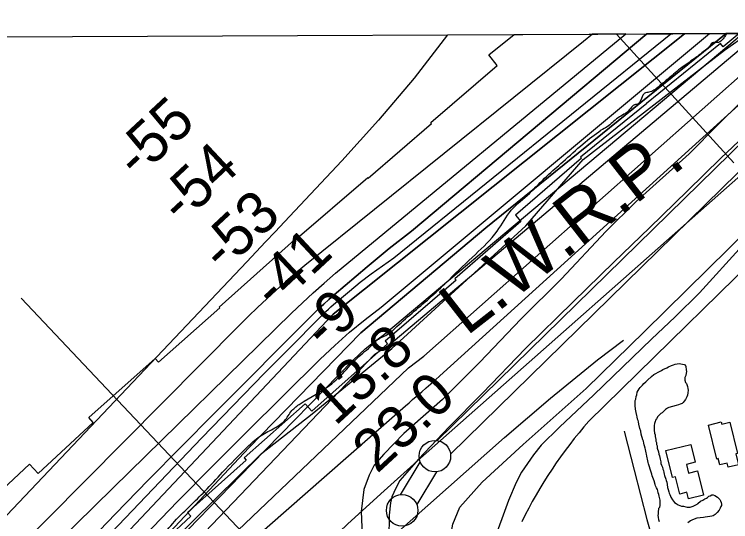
# Model space of a CAD drawing. Extents: x 3424494 to 3462436, y 522220 to 547718.
# Drawn here: x 3452339 to 3453473, y 545132 to 545936 of the extents above; entities that cross this region are included whole.
import ezdxf

# ---------------------------------------------------------------- set-up
doc = ezdxf.new("R2010")
doc.units = 0
for name, color, linetype in [('V-BLDG-OTLN', 7, 'Continuous'), ('V-DTCH-CNTR', 7, 'Continuous'), ('V-FLOD-BASE', 7, 'Continuous'), ('V-GRID-FRAM', 7, 'Continuous'), ('V-LEVE-TOET', 7, 'Continuous'), ('V-RIVR-EDGE', 7, 'Continuous'), ('V-RIVR-RANG', 7, 'Continuous'), ('V-ROAD-CNTR', 7, 'Continuous'), ('V-RRAP-FSHR', 7, 'Continuous'), ('V-RRAP-RVMT', 7, 'Continuous'), ('V-SITE-VEGE', 7, 'Continuous'), ('V-SURV-LINE', 7, 'Continuous'), ('V-TOPO-DPTH', 7, 'Continuous'), ('V-TOPO-MAJR', 7, 'Continuous'), ('V-TOPO-MINR', 7, 'Continuous'), ('V-TOPO-SHOR', 7, 'Continuous'), ('V-TOPO-WATR', 7, 'Continuous'), ('V-TOPO-WATR-IDEN', 7, 'Continuous')]:
    doc.layers.add(name, color=color, linetype=linetype)

msp = doc.modelspace()

# ---------------------------------------------------------------- linework, layer by layer
at = {"layer": 'V-BLDG-OTLN'}
for points in [[(3453450.9, 545231.5), (3453437.9, 545285.3), (3453458.2, 545290.2), (3453459.1, 545286.6), (3453472, 545289.7), (3453484, 545240.3), (3453481.1, 545239.6), (3453485.2, 545222.5), (3453469, 545218.6), (3453467.4, 545225), (3453455.9, 545222.2), (3453453.4, 545232.2)], [(3453380.8, 545202.2), (3453370.2, 545244.8), (3453410, 545254.7), (3453417, 545226.6), (3453402.9, 545223.1), (3453406.4, 545209.1), (3453420.5, 545212.6), (3453430, 545174.5), (3453406.2, 545168.6), (3453403.7, 545178.8), (3453392.4, 545176), (3453385.6, 545203.3)]]:
    msp.add_lwpolyline(points, close=True, dxfattribs=at)
at = {"layer": 'V-DTCH-CNTR'}
msp.add_lwpolyline([(3453304.6, 545275.4), (3453320.2, 545213.7), (3453340.6, 545136), (3453362.8, 545056.4), (3453380.1, 544985), (3453401.2, 544903.1)], dxfattribs=at)
at = {"layer": 'V-FLOD-BASE'}
msp.add_lwpolyline([(3453668.4, 545906.4), (3453642.8, 545882.8), (3453583.2, 545827), (3453524.7, 545771.6), (3453457.6, 545707.8), (3453404.9, 545656.2), (3453344.5, 545597.7), (3453287.9, 545543.1), (3453223.6, 545480.4), (3453148.5, 545406.8), (3453080.1, 545335.7), (3453027.5, 545282.5), (3452979.1, 545231.2), (3452949.6, 545197.7), (3452942.8, 545185.5), (3452936.8, 545171.7), (3452934.7, 545162.4), (3452932.4, 545142.8), (3452931.8, 545105.7), (3452934.7, 545024.5), (3452935.5, 544935.7), (3452937.9, 544845.3)], dxfattribs=at)
at = {"layer": 'V-GRID-FRAM'}
msp.add_lwpolyline([(3428547.8, 545793.2), (3460200.7, 545935.9)], dxfattribs=at)
at = {"layer": 'V-LEVE-TOET'}
for points in [[(3453612, 545906.2), (3453571.2, 545873), (3453521.9, 545829.1), (3453453.3, 545761.3), (3453407.5, 545714.7), (3453323.4, 545639.4), (3453275.6, 545592.1), (3453205.3, 545517), (3453140.7, 545452.9), (3453075.9, 545384.7), (3453016.8, 545325.6), (3452955.7, 545271.9), (3452924, 545239.3), (3452908.7, 545221.8), (3452900.7, 545205.8), (3452892.6, 545183.2), (3452888.2, 545148.2), (3452891, 545086.5), (3452895.6, 544993.5), (3452895, 544891)], [(3453020.2, 544568.3), (3453028.5, 544674.1), (3453037, 544835.8), (3453034, 544953.4), (3453028.8, 545034.7), (3453028.4, 545101.8), (3453033.1, 545128.3), (3453044.3, 545155.4), (3453079.6, 545194.9), (3453144.6, 545254.7), (3453244.3, 545343.5), (3453336.8, 545433.7), (3453470, 545565.1), (3453558.9, 545653), (3453648.5, 545733.9), (3453753.1, 545838.5), (3453818.5, 545907.1)]]:
    msp.add_lwpolyline(points, dxfattribs=at)
at = {"layer": 'V-RIVR-EDGE'}
for points in [[(3453466.8, 545905.5), (3453466.2, 545904.6), (3453463.1, 545899.8), (3453459.2, 545894.9), (3453451.9, 545891.1), (3453444.3, 545890.8), (3453441.8, 545888.7), (3453440.4, 545886.6), (3453438, 545883.1), (3453429.6, 545876.6), (3453420.6, 545869.3), (3453410.1, 545862), (3453405.6, 545858.5), (3453393.4, 545849.9), (3453382.6, 545840.9), (3453364.2, 545825.6), (3453351.6, 545815.6), (3453343.6, 545812.5), (3453337, 545811.1), (3453334.2, 545807.6), (3453329.3, 545797.5), (3453325.8, 545793.7), (3453321, 545792.7), (3453312.6, 545784.4), (3453294.8, 545771.9), (3453277.4, 545757.7), (3453267.7, 545752.5)], [(3451748, 544260.9), (3451764.4, 544271.1), (3451791.5, 544289.6), (3451819.7, 544315.2), (3451837, 544333.4), (3451853.4, 544346.5), (3451865.5, 544357.5), (3451883.9, 544373.5), (3451891.9, 544381.9), (3451901.8, 544389.5), (3451915.4, 544400.1), (3451929.3, 544415.4), (3451940.3, 544428.2), (3451954.2, 544444.2), (3451972.9, 544464.7), (3451993.4, 544482.9), (3452012.5, 544495.6), (3452023.8, 544502.9), (3452039.2, 544516.4), (3452050.2, 544527), (3452059, 544538.3), (3452067.8, 544552.9), (3452074.8, 544560.5), (3452091.2, 544571.8), (3452115.8, 544592.6), (3452128.2, 544602.8), (3452139.6, 544615.2), (3452155, 544628.3), (3452167.4, 544638.5), (3452179.9, 544650.9), (3452198.2, 544669.2), (3452207.8, 544682.3), (3452220.6, 544695.1), (3452238.5, 544714), (3452251, 544727.5), (3452258.3, 544734.8), (3452278.1, 544758.5), (3452293.2, 544775.7), (3452312.6, 544794.6), (3452329.8, 544810.7), (3452335.3, 544823.1), (3452350, 544839.5), (3452364.7, 544859.2), (3452384.1, 544880), (3452409.4, 544913.9), (3452420.8, 544928.9), (3452427.4, 544943.5), (3452428.9, 544959.2), (3452432.2, 544966.5), (3452437.7, 544973.4), (3452456.7, 544992), (3452476.9, 545011.7), (3452493, 545024.9), (3452500.7, 545030.3), (3452509.5, 545042), (3452516.5, 545052.2), (3452530.4, 545063.1), (3452544.7, 545071.1), (3452550.5, 545081), (3452571.8, 545108.4), (3452596, 545136.1), (3452616.9, 545156.9), (3452640.7, 545180.6), (3452668.6, 545210.5), (3452708.1, 545250.6), (3452727.2, 545267), (3452748.8, 545279.4), (3452766.7, 545292.1), (3452778.5, 545308.2), (3452791.7, 545319.1), (3452841.5, 545350.8), (3452868.2, 545377), (3452890.6, 545399.3), (3452902.6, 545409.1), (3452913.3, 545420.1), (3452931.6, 545429.9), (3452944.8, 545441.2), (3452999.7, 545489.3), (3453027.2, 545515.6), (3453069, 545555.7), (3453103.4, 545592.5), (3453125.8, 545625.7), (3453154.4, 545652.3), (3453181.9, 545679.7), (3453207.5, 545702.3), (3453239.4, 545730.7), (3453267.7, 545752.5)]]:
    msp.add_spline(points, degree=3, dxfattribs=at)
at = {"layer": 'V-RIVR-RANG'}
for p, q in [((3453477.9, 545700.6), (3453292.3, 545904.7)), ((3452954.2, 544846.8), (3452349.9, 545486.5))]:
    msp.add_line(p, q, dxfattribs=at)
at = {"layer": 'V-ROAD-CNTR'}
msp.add_lwpolyline([(3453884.7, 545910.6), (3453846.8, 545876.3), (3453583.6, 545619.9), (3453248.6, 545291.6)], dxfattribs=at)
msp.add_arc((3453799.9, 544808.8), 732.8, 138.7864, 153.8044, dxfattribs=at)
at = {"layer": 'V-RRAP-FSHR'}
msp.add_lwpolyline([(3452428.4, 544915), (3452485.2, 544969.8), (3452549.1, 545061.3), (3452730.6, 545240.1), (3452810.8, 545303.1), (3452936.8, 545406.4), (3453148.6, 545600.9), (3453239.6, 545706), (3453463.4, 545878.9), (3453500.8, 545905.7)], dxfattribs=at)
at = {"layer": 'V-RRAP-RVMT'}
for p, q in [((3453090.1, 545871.6), (3453130.1, 545904)), ((3453130.1, 545904), (3453486.3, 545905.6)), ((3453486.3, 545905.6), (3453461.1, 545884.6)), ((3453456.8, 545889.8), (3453340, 545794.9)), ((3453461.1, 545884.6), (3453456.8, 545889.8)), ((3453103.6, 545854.9), (3453090.1, 545871.6)), ((3452998.5, 545764.3), (3453103.6, 545854.9)), ((3453340.3, 545794.5), (3453235.5, 545709.6)), ((3453340, 545794.9), (3453340.3, 545794.5)), ((3452899.4, 545676.4), (3452999.4, 545763.1)), ((3452999.4, 545763.1), (3452998.5, 545764.3)), ((3453237, 545707.8), (3453132.6, 545617.7)), ((3453235.5, 545709.6), (3453237, 545707.8)), ((3452783.3, 545578.2), (3452898.6, 545677.3)), ((3452898.6, 545677.3), (3452899.4, 545676.4)), ((3453132.6, 545617.7), (3453141, 545608)), ((3453141, 545608), (3453036.2, 545517.2)), ((3452663.1, 545472.3), (3452782.7, 545578.9)), ((3452782.7, 545578.9), (3452783.3, 545578.2)), ((3453038.3, 545514.7), (3452926, 545418.1)), ((3453036.2, 545517.2), (3453038.3, 545514.7)), ((3452567.5, 545385), (3452664.3, 545470.9)), ((3452664.3, 545470.9), (3452663.1, 545472.3)), ((3452926, 545418.1), (3452929.6, 545414)), ((3452929.6, 545414), (3452810, 545307.4)), ((3452457.1, 545297.1), (3452562.1, 545390.9)), ((3452562.1, 545390.9), (3452567.5, 545385)), ((3452799.5, 545319.1), (3452702.9, 545233.3)), ((3452810, 545307.4), (3452799.5, 545319.1)), ((3452463.9, 545289.4), (3452457.1, 545297.1)), ((3452377, 545208.4), (3452463.9, 545289.4)), ((3452299.5, 545164.3), (3452363.1, 545223.4)), ((3452363.1, 545223.4), (3452377, 545208.4)), ((3452706.2, 545229.7), (3452613.2, 545146.6)), ((3452702.9, 545233.3), (3452706.2, 545229.7)), ((3452613.2, 545146.6), (3452618.3, 545141.2)), ((3452618.3, 545141.2), (3452522.4, 545051.7))]:
    msp.add_line(p, q, dxfattribs=at)
at = {"layer": 'V-SITE-VEGE'}
for points in [[(3453323.6, 545330.6), (3453324.4, 545333.3), (3453325.3, 545337.2), (3453326.5, 545340.2), (3453328.4, 545342.9), (3453329.6, 545344.8), (3453333.5, 545348.6), (3453335.5, 545350.9), (3453338.6, 545353.9), (3453341.4, 545356.2), (3453347.6, 545362.2), (3453351.5, 545365.2), (3453361.3, 545370.8), (3453363.6, 545372), (3453365.6, 545373.5), (3453372.2, 545376.1), (3453374.9, 545377.6), (3453379.5, 545379.8), (3453382.3, 545380.5), (3453385.4, 545381.6), (3453388.5, 545382.3), (3453391.5, 545382.7), (3453399.2, 545381.4), (3453401.1, 545380.6), (3453401.9, 545377.9), (3453402.6, 545372.8), (3453403.3, 545370.1), (3453402.8, 545367.4), (3453402, 545363.6), (3453400.4, 545360.6), (3453400.7, 545356.3), (3453401.8, 545352.8), (3453403, 545350.9), (3453404.8, 545346.2), (3453405.5, 545343.5), (3453405.9, 545340.4), (3453405.4, 545336.2), (3453404.6, 545332.7), (3453403.8, 545330), (3453401.8, 545325.8), (3453399.4, 545323.2), (3453397.8, 545320.9), (3453396.3, 545319.4), (3453393.2, 545318.3), (3453390.4, 545317.6), (3453387, 545316.5), (3453375, 545313.2), (3453373, 545312.1), (3453369.9, 545309.8), (3453364.8, 545304.9), (3453362.5, 545303.4), (3453357.8, 545298.8), (3453355.4, 545295.4), (3453354.2, 545293.1), (3453353.4, 545291.2), (3453352.6, 545287.7), (3453352.1, 545284.7), (3453351.7, 545280.8), (3453352, 545277.3), (3453352.7, 545272.7), (3453353.4, 545270), (3453353.4, 545267.3), (3453354.4, 545262.3), (3453354.8, 545259.6), (3453355.5, 545257.6), (3453355.5, 545254.5), (3453356.6, 545252.2), (3453356.9, 545248.7), (3453358.7, 545242.9), (3453359.4, 545239.1), (3453360.2, 545236.4), (3453361.2, 545231.3), (3453362.3, 545227.1), (3453362.7, 545224.7), (3453363.4, 545222), (3453364.9, 545218.9), (3453365.6, 545215.4), (3453366.7, 545213.5), (3453367.1, 545210.4), (3453367.8, 545207.3), (3453368.5, 545205.4), (3453370.3, 545199.6), (3453371.1, 545197.6), (3453371.8, 545194.9), (3453372.5, 545191.4), (3453373.2, 545186.4), (3453374.3, 545183.3), (3453375, 545179.8), (3453375.7, 545177.5), (3453376.9, 545175.6), (3453377.6, 545172.9), (3453378.3, 545170.9), (3453381, 545167), (3453384.4, 545162.7), (3453387, 545161.1), (3453389.7, 545159.2), (3453392.4, 545158), (3453395.1, 545157.1), (3453398.5, 545156.7), (3453402, 545155.9), (3453404.3, 545155.4)], [(3453360.3, 545132.3), (3453359.2, 545135.4), (3453358.9, 545139.2), (3453358.2, 545142.3), (3453358.6, 545144.7), (3453358.7, 545147), (3453359.5, 545153.5), (3453360.7, 545155.4), (3453361.2, 545157.7), (3453361.2, 545161.6), (3453361.7, 545166.2), (3453360.6, 545170.8), (3453359.9, 545172.8), (3453359.5, 545175.1), (3453358.4, 545177.8), (3453357.7, 545180.9), (3453357, 545183.2), (3453355.5, 545185.9), (3453354, 545189.1), (3453353.6, 545191.4), (3453351.8, 545197.2), (3453350.7, 545199.5), (3453348.8, 545204.9), (3453348.1, 545207.7), (3453347, 545210.8), (3453343, 545223.9), (3453342.7, 545226.2), (3453341.9, 545228.6), (3453340.5, 545235.9), (3453339.8, 545239), (3453339.1, 545241.3), (3453338.4, 545246.4), (3453337.6, 545248.7), (3453336.9, 545252.2), (3453336.2, 545254.1), (3453335.5, 545256.4), (3453335.1, 545259.9), (3453334, 545261.8), (3453331.5, 545271.1), (3453330.8, 545275.4), (3453329.3, 545280), (3453327.9, 545286.6), (3453327.2, 545290.5), (3453326.4, 545292.8), (3453325.7, 545294.7), (3453325, 545298.2), (3453324.6, 545300.5), (3453323.6, 545305.2), (3453323.2, 545307.9), (3453322.5, 545310.6), (3453321.8, 545316.4), (3453321.9, 545324.1), (3453322.8, 545326.4), (3453323.6, 545330.6)], [(3453425.3, 545164.7), (3453429.1, 545166.6), (3453432.3, 545168.5), (3453434.6, 545169.6), (3453436.5, 545170.7), (3453438.5, 545172.6), (3453440.8, 545173.3), (3453443.2, 545174.8), (3453445.5, 545174.8), (3453448.1, 545174), (3453452.3, 545171.2), (3453454.2, 545169.2), (3453455.7, 545167.3), (3453456.9, 545165.3), (3453458, 545162.6), (3453458.3, 545160.3), (3453458.3, 545158), (3453457.5, 545156.1), (3453456.7, 545153.8), (3453455.1, 545150.3), (3453451.9, 545146.9), (3453448.4, 545143.5), (3453445.3, 545141.6), (3453443, 545140.9), (3453440.3, 545140.6), (3453436.4, 545139.9), (3453432.5, 545139.6), (3453429.8, 545138.8), (3453419.4, 545137.8), (3453412.4, 545135.3), (3453409.3, 545133.8), (3453405, 545130.4)], [(3453404.3, 545155.4), (3453408.9, 545155.4), (3453413.6, 545156.8), (3453415.9, 545157.9), (3453417.8, 545159.1), (3453419.8, 545159.8), (3453421.3, 545161.3), (3453425.3, 545164.7)]]:
    msp.add_lwpolyline(points, dxfattribs=at)
at = {"layer": 'V-SURV-LINE'}
for points in [[(3453008.6, 545260.7), (3453667.8, 545906.4)], [(3453710.9, 545906.6), (3453029.6, 545239.3)], [(3453710.9, 545906.6), (3453029.6, 545239.3)], [(3452950.5, 545175), (3452981.7, 545226.7)], [(3452950.5, 545175), (3452981.7, 545226.7)], [(3453007.3, 545211.2), (3452976.1, 545159.5)], [(3453007.3, 545211.2), (3452976.1, 545159.5)]]:
    msp.add_lwpolyline(points, dxfattribs=at)
for centre in [(3453004.8, 545236.1), (3452953, 545150.2)]:
    msp.add_circle(centre, 25, dxfattribs=at)
at = {"layer": 'V-TOPO-DPTH'}
for p, q in [((3453307.2, 545904.8), (3453254.6, 545904.6)), ((3453400.2, 545905.2), (3453340.1, 545905)), ((3453466, 545905.5), (3453400.2, 545905.2)), ((3453517.1, 545905.8), (3453466, 545905.5))]:
    msp.add_line(p, q, dxfattribs=at)
for points in [[(3449093.9, 542021.4), (3449331, 542199.6), (3449457.3, 542301.4), (3450025.6, 542795.6), (3450435, 543123.2), (3450672.2, 543320.1), (3451252.5, 543851.7), (3451390.8, 543980.8), (3451645, 544201.5), (3451971, 544483.4), (3452039.2, 544549.6), (3452411.4, 544916.5), (3452437, 544957.3), (3452710.2, 545249.5), (3452887.7, 545431.3), (3453085.7, 545597.7), (3453466, 545905.5)], [(3453466, 545905.5), (3453085.7, 545597.7), (3452887.7, 545431.3), (3452710.2, 545249.5), (3452437, 544957.3), (3452411.4, 544916.5), (3452039.2, 544549.6), (3451971, 544483.4), (3451645, 544201.5), (3451390.8, 543980.8), (3451252.5, 543851.7), (3450672.2, 543320.1), (3450435, 543123.2), (3450025.6, 542795.6), (3449457.3, 542301.4), (3449331, 542199.6), (3449093.9, 542021.4)], [(3451909.4, 544601.6), (3451925.9, 544617.6), (3451942.2, 544633.6), (3452201.2, 544889.1), (3452221.3, 544909), (3452241.3, 544928.9), (3452261.2, 544949), (3452281.1, 544969.1), (3452300.9, 544989.2), (3452320.7, 545009.4), (3452340.5, 545029.6), (3452360.2, 545049.8), (3452378.6, 545068.7), (3452407.6, 545098.3), (3452436.7, 545127.7), (3452466.1, 545156.9), (3452495.6, 545186), (3452778.1, 545462.5), (3452795, 545478.7), (3452812.2, 545494.7), (3452829.6, 545510.3), (3452847.3, 545525.7), (3453307.2, 545904.8)], [(3451909.4, 544601.6), (3451925.9, 544617.6), (3451942.2, 544633.6), (3452201.2, 544889.1), (3452221.3, 544909), (3452241.3, 544928.9), (3452261.2, 544949), (3452281.1, 544969.1), (3452300.9, 544989.2), (3452320.7, 545009.4), (3452340.5, 545029.6), (3452360.2, 545049.8), (3452378.6, 545068.7), (3452407.6, 545098.3), (3452436.7, 545127.7), (3452466.1, 545156.9), (3452495.6, 545186), (3452778.1, 545462.5), (3452795, 545478.7), (3452812.2, 545494.7), (3452829.6, 545510.3), (3452847.3, 545525.7), (3453307.2, 545904.8)], [(3451976.2, 544562.9), (3452040, 544624.9), (3452078.9, 544663.1), (3452117.6, 544701.3), (3452156, 544739.9), (3452194.3, 544778.7), (3452329.3, 544916.7), (3452349.6, 544937.5), (3452369.8, 544958.4), (3452389.8, 544979.5), (3452409.8, 545000.6), (3452842.8, 545460.1), (3452843.6, 545460.9), (3452843.8, 545461), (3452844, 545461.1), (3453400.2, 545905.2)], [(3453400.2, 545905.2), (3452844, 545461.1), (3452843.8, 545461), (3452843.6, 545460.9), (3452842.8, 545460.1), (3452409.8, 545000.6), (3452389.8, 544979.5), (3452369.8, 544958.4), (3452349.6, 544937.5), (3452329.3, 544916.7), (3452194.3, 544778.7), (3452156, 544739.9), (3452117.6, 544701.3), (3452078.9, 544663.1), (3452040, 544624.9), (3451976.2, 544562.9)], [(3452144, 544594.2), (3452171.9, 544623.2), (3452199.6, 544652.3), (3452399.2, 544862.3), (3452414.8, 544878.8), (3452430.5, 544895.3), (3452446.2, 544911.9), (3452461.8, 544928.4), (3452909.3, 545397.1), (3452913, 545399.8), (3452915.9, 545401.8), (3452921.2, 545405.3), (3452926.5, 545408.7), (3452931.9, 545412.1), (3453513.6, 545902.4), (3453517.1, 545905.8)], [(3453254.6, 545904.6), (3453240.3, 545892.9), (3452799.1, 545538.1), (3452783.7, 545525.2), (3452768.5, 545512.1), (3452753.5, 545498.9), (3452738.7, 545485.4), (3452724, 545471.7), (3452709.6, 545457.7), (3452695.3, 545443.6), (3452330.2, 545075.2)], [(3453254.6, 545904.6), (3453240.3, 545892.9), (3452799.1, 545538.1), (3452783.7, 545525.2), (3452768.5, 545512.1), (3452753.5, 545498.9), (3452738.7, 545485.4), (3452724, 545471.7), (3452709.6, 545457.7), (3452695.3, 545443.6), (3452330.2, 545075.2)], [(3453340.1, 545905), (3452967.9, 545592.7), (3452932.3, 545564.8), (3452897.4, 545536), (3452845.3, 545491.6), (3452837, 545484.3), (3452828.8, 545476.9), (3452820.7, 545469.3), (3452812.8, 545461.5), (3452655.5, 545303.5), (3452603.2, 545250.8), (3452551.2, 545197.9), (3452499.4, 545144.7), (3452447.9, 545091.3), (3452360.4, 545000.2), (3452352.7, 544992.2), (3452345, 544984.2), (3452337.2, 544976.3)], [(3453340.1, 545905), (3452967.9, 545592.7), (3452932.3, 545564.8), (3452897.4, 545536), (3452845.3, 545491.6), (3452837, 545484.3), (3452828.8, 545476.9), (3452820.7, 545469.3), (3452812.8, 545461.5), (3452655.5, 545303.5), (3452603.2, 545250.8), (3452551.2, 545197.9), (3452499.4, 545144.7), (3452447.9, 545091.3), (3452360.4, 545000.2), (3452352.7, 544992.2), (3452345, 544984.2), (3452337.2, 544976.3)]]:
    msp.add_lwpolyline(points, dxfattribs=at)
at = {"layer": 'V-TOPO-MAJR'}
for points in [[(3453025, 545903.5), (3453024.9, 545903.4), (3452971.8, 545834.7), (3452915.7, 545768.5), (3452857.6, 545703.9), (3452766.8, 545607.3), (3452751.9, 545591.4), (3452736.9, 545575.5), (3452722, 545559.7), (3452707, 545543.9), (3452260.3, 545072.2), (3451769.3, 544740.1), (3451749.9, 544721.2), (3451731.3, 544701.3), (3451670.6, 544631.8), (3451629.2, 544584)], [(3452078.6, 544454.1), (3452542.5, 544828.7), (3452569.4, 544850.3), (3452580.4, 544859.4), (3452612.2, 544886.3), (3452643.5, 544913.8), (3452674, 544942.1), (3452704.1, 544971), (3452755.2, 545021.4), (3452810.9, 545075.3), (3452867.2, 545128.7), (3452924.3, 545181.1), (3452982, 545233), (3453520.6, 545708.9), (3453652.2, 545821.2), (3453757.7, 545906.8)]]:
    msp.add_lwpolyline(points, dxfattribs=at)
at = {"layer": 'V-TOPO-MINR'}
for points in [[(3451909.4, 544601.6), (3451925.9, 544617.6), (3451942.2, 544633.6), (3452201.2, 544889.1), (3452221.3, 544909), (3452241.3, 544928.9), (3452261.2, 544949), (3452281.1, 544969.1), (3452300.9, 544989.2), (3452320.7, 545009.4), (3452340.5, 545029.6), (3452360.2, 545049.8), (3452378.6, 545068.7), (3452407.6, 545098.3), (3452436.7, 545127.7), (3452466.1, 545156.9), (3452495.6, 545186), (3452778.1, 545462.5), (3452795, 545478.7), (3452812.2, 545494.7), (3452829.6, 545510.3), (3452847.3, 545525.7), (3453307.2, 545904.8)], [(3451955.1, 544571.1), (3452329.1, 544945.1), (3452342.7, 544958.8), (3452356.2, 544972.5), (3452369.7, 544986.4), (3452383, 545000.3), (3452635.3, 545264.4), (3452668.4, 545298.8), (3452701.7, 545333.1), (3452735.1, 545367.3), (3452768.7, 545401.3), (3452828.2, 545461.2), (3452832.2, 545465.1), (3452836.2, 545468.9), (3452840.3, 545472.6), (3452844.5, 545476.2), (3452869.6, 545497.5), (3452886.6, 545511.4), (3452903.9, 545524.8), (3452921.7, 545537.6), (3452939.9, 545550), (3453378.5, 545905.1)], [(3451976.2, 544562.9), (3452040, 544624.9), (3452078.9, 544663.1), (3452117.6, 544701.3), (3452156, 544739.9), (3452194.3, 544778.7), (3452329.3, 544916.7), (3452349.6, 544937.5), (3452369.8, 544958.4), (3452389.8, 544979.5), (3452409.8, 545000.6), (3452842.8, 545460.1), (3452843.6, 545460.9), (3452843.8, 545461), (3452844, 545461.1), (3453400.2, 545905.2)], [(3452005.3, 544562.8), (3452218.4, 544772.2), (3452246.6, 544800.1), (3452274.7, 544828.2), (3452302.6, 544856.5), (3452330.3, 544885), (3452357.9, 544913.6), (3452385.4, 544942.2), (3452412.8, 544971), (3452440.1, 544999.8), (3452491.3, 545053.9), (3452544.5, 545109.5), (3452598, 545164.8), (3452652.1, 545219.6), (3452706.5, 545274), (3452823.1, 545389.6), (3452846.2, 545411.4), (3452869.9, 545432.6), (3452894.5, 545452.6), (3452919.7, 545471.9), (3453439.3, 545905.4)], [(3452035.2, 544507.1), (3452399.1, 544892.9), (3452407.5, 544901.8), (3452415.8, 544910.6), (3452424.1, 544919.4), (3452432.4, 544928.3), (3452514.7, 545015.6), (3452564.3, 545067.9), (3452614.1, 545120.1), (3452664.2, 545171.9), (3452714.5, 545223.6), (3452875.6, 545388.2), (3452885, 545397.3), (3452894.6, 545406), (3452904.7, 545414.2), (3452915.1, 545422.1), (3452924.9, 545429.1), (3453483.3, 545898), (3453491.2, 545905.6)], [(3452144, 544594.2), (3452171.9, 544623.2), (3452199.6, 544652.3), (3452399.2, 544862.3), (3452414.8, 544878.8), (3452430.5, 544895.3), (3452446.2, 544911.9), (3452461.8, 544928.4), (3452909.3, 545397.1), (3452913, 545399.8), (3452915.9, 545401.8), (3452921.2, 545405.3), (3452926.5, 545408.7), (3452931.9, 545412.1), (3453513.6, 545902.4), (3453517.1, 545905.8)], [(3452172.7, 544598.3), (3452218.5, 544644.9), (3452264.1, 544691.6), (3452309.6, 544738.5), (3452354.9, 544785.6), (3452422.2, 544856), (3452433.7, 544868), (3452445.2, 544880), (3452456.8, 544892), (3452468.3, 544904), (3452963.2, 545376.2), (3452987.1, 545394.2), (3453516.2, 545863.2), (3453559.8, 545906)], [(3453254.6, 545904.6), (3453240.3, 545892.9), (3452799.1, 545538.1), (3452783.7, 545525.2), (3452768.5, 545512.1), (3452753.5, 545498.9), (3452738.7, 545485.4), (3452724, 545471.7), (3452709.6, 545457.7), (3452695.3, 545443.6), (3452330.2, 545075.2)], [(3452337.2, 544976.3), (3452345, 544984.2), (3452352.7, 544992.2), (3452360.4, 545000.2), (3452447.9, 545091.3), (3452499.4, 545144.7), (3452551.2, 545197.9), (3452603.2, 545250.8), (3452655.5, 545303.5), (3452812.8, 545461.5), (3452820.7, 545469.3), (3452828.8, 545476.9), (3452837, 545484.3), (3452845.3, 545491.6), (3452897.4, 545536), (3452932.3, 545564.8), (3452967.9, 545592.7), (3453340.1, 545905)], [(3452614.6, 545014.1), (3452958.2, 545315.7), (3452963.9, 545320.6), (3452969.6, 545325.6), (3452975.3, 545330.5), (3452981, 545335.4), (3452984, 545338), (3452991.2, 545344.2), (3452998.4, 545350.5), (3453005.6, 545356.8), (3453012.7, 545363.2), (3453530.3, 545832.8)], [(3452457.5, 544624.3), (3452527.2, 544708.9), (3452546.6, 544731.7), (3452566.4, 544754.2), (3452586.8, 544776.2), (3452607.6, 544797.8), (3452656.5, 544847.2), (3452702.5, 544892.8), (3452749.1, 544937.8), (3452796.5, 544981.9), (3452844.5, 545025.3), (3453114.8, 545265.5), (3453187.8, 545328), (3453262.3, 545388.6), (3453303.4, 545419.7)]]:
    msp.add_lwpolyline(points, dxfattribs=at)
at = {"layer": 'V-TOPO-SHOR'}
msp.add_lwpolyline([(3453492, 545569.8), (3453423.6, 545495), (3453385.3, 545456.6), (3453347.7, 545421.6), (3453256.5, 545333.4), (3453202.2, 545282.2), (3453173, 545253.3), (3453161.1, 545238), (3453142.1, 545210.9), (3453133.7, 545194.6), (3453121.5, 545166), (3453096.4, 545098), (3453083.4, 545056.4), (3453078.2, 545033.2), (3453075.9, 545016.1), (3453069.6, 544926.5), (3453062.1, 544805.4), (3453056.5, 544718.5), (3453046.6, 544618.7), (3453035.7, 544540.1)], dxfattribs=at)
at = {"layer": 'V-TOPO-WATR'}
msp.add_lwpolyline([(3453466, 545905.5), (3453085.7, 545597.7), (3452887.7, 545431.3), (3452710.2, 545249.5), (3452437, 544957.3), (3452411.4, 544916.5), (3452039.2, 544549.6), (3451971, 544483.4), (3451645, 544201.5), (3451390.8, 543980.8), (3451252.5, 543851.7), (3450672.2, 543320.1), (3450435, 543123.2), (3450025.6, 542795.6), (3449457.3, 542301.4), (3449331, 542199.6), (3449093.9, 542021.4)], dxfattribs=at)

# ---------------------------------------------------------------- texts
at = {"layer": 'V-RIVR-RANG'}
for s, rotation, p in [('-55', 43.0826, (3452534, 545673.3)), ('-54', 43.0826, (3452603.5, 545601.4)), ('-53', 43.0826, (3452669.1, 545525.8)), ('-41', 43.0826, (3452751.3, 545465.8)), ('-9', 43.0826, (3452830.6, 545403)), ('13.8', 42.7983, (3452847.3, 545282.6)), ('23.0', 42.7983, (3452913.3, 545207.4))]:
    msp.add_text(s, height=67, rotation=rotation, dxfattribs=at).set_placement(p)
at = {"layer": 'V-TOPO-WATR-IDEN'}
msp.add_text('L.W.R.P.', height=83, rotation=37.9593, dxfattribs=at).set_placement((3453054.7, 545425.2))

doc.saveas('drawing.dxf')
